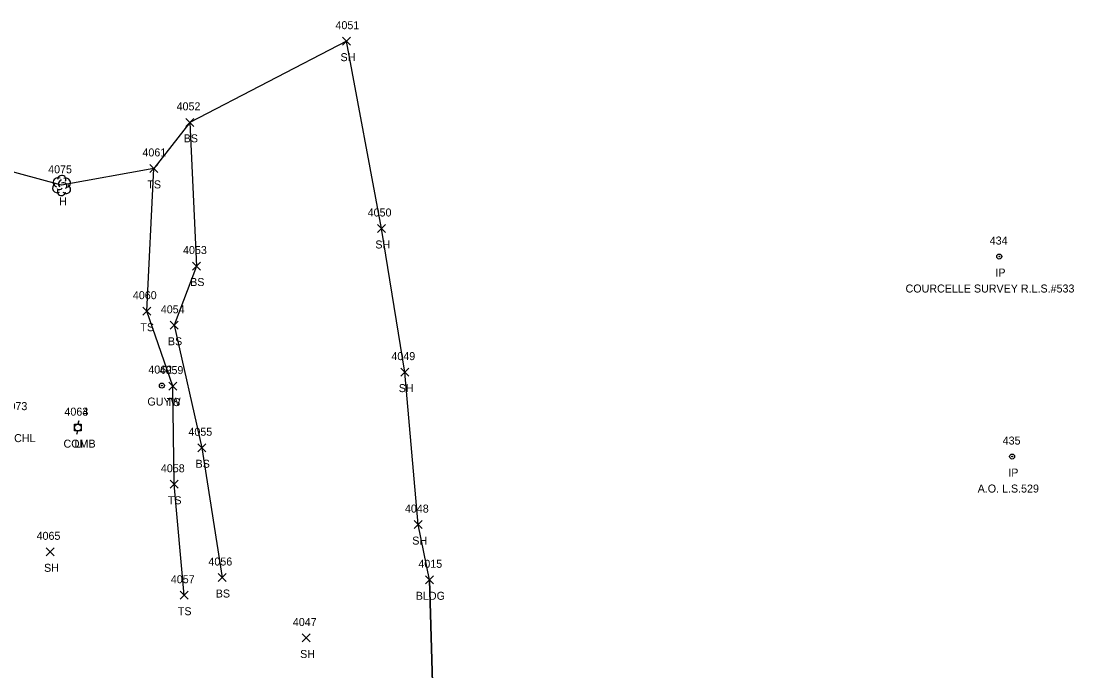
# Model space of a CAD drawing. Extents: x 1509053 to 1511576, y 400838 to 402572.
# Drawn here: x 1510649 to 1510912.2, y 401775.8 to 401938.3 of the extents above; entities that cross this region are included whole.
import ezdxf

# ---------------------------------------------------------------- set-up
doc = ezdxf.new("R2010")
doc.units = 0
for name, color, linetype in [('L_A', 7, 'Continuous'), ('L_I', 7, 'Continuous'), ('L_TIC', 7, 'Continuous'), ('LBC', 7, 'Continuous'), ('LELB', 7, 'Continuous'), ('LSOGP', 7, 'Continuous'), ('LTD', 7, 'Continuous'), ('M_A', 7, 'Continuous'), ('M_C', 7, 'Continuous'), ('M_I', 7, 'Continuous'), ('MPIR', 7, 'Continuous'), ('U_A', 7, 'Continuous'), ('U_I', 7, 'Continuous'), ('ULP', 7, 'Continuous'), ('UP', 7, 'Continuous'), ('UPGW', 7, 'Continuous')]:
    doc.layers.add(name, color=color, linetype=linetype)

msp = doc.modelspace()

# ---------------------------------------------------------------- linework, layer by layer
at = {"layer": 'L_TIC'}
for points in [[(1510729.41, 401932.32), (1510731.41, 401934.32)], [(1510731.41, 401932.32), (1510729.41, 401934.32)], [(1510690.26, 401912.02), (1510692.26, 401914.02)], [(1510692.26, 401912.02), (1510690.26, 401914.02)], [(1510681.2, 401900.5), (1510683.2, 401902.5)], [(1510683.2, 401900.5), (1510681.2, 401902.5)], [(1510738.11, 401885.48), (1510740.11, 401887.48)], [(1510740.11, 401885.48), (1510738.11, 401887.48)], [(1510691.87, 401876.09), (1510693.87, 401878.09)], [(1510693.87, 401876.09), (1510691.87, 401878.09)], [(1510679.46, 401864.8), (1510681.46, 401866.8)], [(1510681.46, 401864.8), (1510679.46, 401866.8)], [(1510686.31, 401861.27), (1510688.31, 401863.27)], [(1510688.31, 401861.27), (1510686.31, 401863.27)], [(1510743.97, 401849.56), (1510745.97, 401851.56)], [(1510745.97, 401849.56), (1510743.97, 401851.56)], [(1510686.01, 401846.07), (1510688.01, 401848.07)], [(1510688.01, 401846.07), (1510686.01, 401848.07)], [(1510693.22, 401830.65), (1510695.22, 401832.65)], [(1510695.22, 401830.65), (1510693.22, 401832.65)], [(1510686.33, 401821.52), (1510688.33, 401823.52)], [(1510688.33, 401821.52), (1510686.33, 401823.52)], [(1510747.34, 401811.44), (1510749.34, 401813.44)], [(1510749.34, 401811.44), (1510747.34, 401813.44)], [(1510655.3, 401804.63), (1510657.3, 401806.63)], [(1510657.3, 401804.63), (1510655.3, 401806.63)], [(1510698.27, 401798.2), (1510700.27, 401800.2)], [(1510700.27, 401798.2), (1510698.27, 401800.2)], [(1510750.13, 401797.63), (1510752.13, 401799.63)], [(1510752.13, 401797.63), (1510750.13, 401799.63)], [(1510688.82, 401793.77), (1510690.82, 401795.77)], [(1510690.82, 401793.77), (1510688.82, 401795.77)], [(1510719.32, 401783.08), (1510721.32, 401785.08)], [(1510721.32, 401783.08), (1510719.32, 401785.08)]]:
    msp.add_lwpolyline(points, dxfattribs=at)
at = {"layer": 'LBC'}
msp.add_lwpolyline([(1510751.13, 401798.63), (1510752.08, 401767.19), (1510771.96, 401767.6), (1510772.1, 401764.08), (1510822.61, 401765.33)], dxfattribs=at)
at = {"layer": 'LELB'}
for points in [[(1510691.26, 401913.02), (1510692.87, 401877.09), (1510687.31, 401862.27), (1510694.22, 401831.65), (1510699.27, 401799.2)], [(1510689.82, 401794.77), (1510687.33, 401822.52), (1510687.01, 401847.07), (1510680.46, 401865.8), (1510682.2, 401901.5)]]:
    msp.add_lwpolyline(points, dxfattribs=at)
at = {"layer": 'LSOGP'}
msp.add_lwpolyline([(1510752.08, 401767.19), (1510751.13, 401798.63), (1510748.34, 401812.44), (1510744.97, 401850.56), (1510739.11, 401886.48), (1510730.41, 401933.32), (1510691.26, 401913.02), (1510682.2, 401901.5), (1510659.15, 401897.28), (1510643.42, 401901.55)], dxfattribs=at)
at = {"layer": 'LTD'}
msp.add_line((1510659.15, 401897.28), (1510659.15, 401897.28), dxfattribs=at)
msp.add_line((1510659.15, 401897.28), (1510659.15, 401897.28), dxfattribs=at)
msp.add_arc((1510659.2, 401898.71), 1.05, 335.5272, 180.9563, dxfattribs=at)
for centre, major_axis, ratio, start_param, end_param in [((1510658.07, 401896.57), (0.58, -1.04), 0.959034, 3.141593, 6.283185), ((1510658.36, 401897.95), (1.21, -0.51), 0.895232, 1.570796, 4.712389), ((1510658.94, 401897.74), (-0.208, -0.792), 0.645439, 3.141593, 6.283185), ((1510659.65, 401897.11), (-0.5, 0.667), 0.989748, 3.141593, 6.283185), ((1510660.15, 401896.45), (-1.09, 0.79), 0.841452, 1.570796, 4.712389), ((1510660.19, 401897.86), (-1.14, -0.48), 0.949671, 1.570796, 4.712389), ((1510659.15, 401895.78), (0.26, 1.06), 0.942809, 1.570796, 4.712389), ((1510658.69, 401896.53), (-0.625, -0.083), 0.423636, 0, 3.141593)]:
    msp.add_ellipse(centre, major_axis=major_axis, ratio=ratio, start_param=start_param, end_param=end_param, dxfattribs=at)
at = {"layer": 'MPIR'}
for centre, radius in [((1510893.57, 401879.47), 0.625), ((1510893.57, 401879.47), 0.0833), ((1510896.79, 401829.45), 0.625), ((1510896.79, 401829.45), 0.0833)]:
    msp.add_circle(centre, radius, dxfattribs=at)
at = {"layer": 'ULP'}
for p, q in [((1510662.43, 401835.85), (1510662.43, 401837.51)), ((1510662.43, 401837.51), (1510664.09, 401837.51)), ((1510663.43, 401838.35), (1510663.26, 401837.51)), ((1510664.09, 401837.51), (1510664.09, 401835.85)), ((1510664.09, 401835.85), (1510662.43, 401835.85)), ((1510663.01, 401835.01), (1510663.26, 401835.85)), ((1510663.26, 401836.68), (1510663.26, 401836.68))]:
    msp.add_line(p, q, dxfattribs=at)
at = {"layer": 'UP'}
for p, q in [((1510662.43, 401835.85), (1510662.43, 401837.51)), ((1510662.43, 401837.51), (1510664.09, 401837.51)), ((1510663.51, 401838.35), (1510663.26, 401837.51)), ((1510664.09, 401837.51), (1510664.09, 401835.85)), ((1510664.09, 401835.85), (1510662.43, 401835.85)), ((1510663.01, 401835.01), (1510663.26, 401835.85)), ((1510663.26, 401836.68), (1510663.26, 401836.68))]:
    msp.add_line(p, q, dxfattribs=at)
msp.add_circle((1510663.26, 401836.68), 0.833, dxfattribs=at)
at = {"layer": 'UPGW'}
for radius in [0.625, 0.0833]:
    msp.add_circle((1510684.23, 401847.2), radius, dxfattribs=at)

# ---------------------------------------------------------------- texts
at = {"layer": 'L_A'}
for s, p in [('SH', (1510728.9, 401928.32)), ('BS', (1510689.7, 401908.02)), ('TS', (1510680.61, 401896.5)), ('H', (1510658.58, 401892.28)), ('SH', (1510737.6, 401881.48)), ('BS', (1510691.31, 401872.09)), ('TS', (1510678.87, 401860.8)), ('BS', (1510685.75, 401857.27)), ('SH', (1510743.46, 401845.56)), ('TS', (1510685.42, 401842.07)), ('FNCHL', (1510643.74, 401833.06)), ('BS', (1510692.66, 401826.65)), ('TS', (1510685.74, 401817.52)), ('SH', (1510746.83, 401807.44)), ('SH', (1510654.79, 401800.63)), ('BS', (1510697.71, 401794.2)), ('BLDG', (1510747.72, 401793.63)), ('TS', (1510688.23, 401789.77)), ('SH', (1510718.81, 401779.08))]:
    msp.add_text(s, height=2, dxfattribs=at).set_placement(p)
at = {"layer": 'L_I'}
for s, p in [('4051', (1510727.64, 401936.32)), ('4052', (1510687.92, 401916.02)), ('4061', (1510679.38, 401904.5)), ('4075', (1510655.81, 401900.28)), ('4050', (1510735.69, 401889.48)), ('4053', (1510689.53, 401880.09)), ('4060', (1510676.99, 401868.8)), ('4054', (1510683.97, 401865.27)), ('4049', (1510741.62, 401853.56)), ('4059', (1510683.66, 401850.07)), ('4073', (1510644.65, 401841.06)), ('4055', (1510690.88, 401834.65)), ('4058', (1510683.99, 401825.52)), ('4048', (1510745, 401815.44)), ('4065', (1510652.92, 401808.63)), ('4056', (1510695.88, 401802.2)), ('4015', (1510748.36, 401801.63)), ('4057', (1510686.48, 401797.77)), ('4047', (1510716.98, 401787.08))]:
    msp.add_text(s, height=2, dxfattribs=at).set_placement(p)
at = {"layer": 'M_A'}
for p in [(1510892.61, 401874.47), (1510895.84, 401824.45)]:
    msp.add_text('IP', height=2, dxfattribs=at).set_placement(p)
at = {"layer": 'M_C'}
for s, p in [('COURCELLE SURVEY R.L.S.#533', (1510870.15, 401870.47)), ('A.O. L.S.529', (1510888.18, 401820.45))]:
    msp.add_text(s, height=2, dxfattribs=at).set_placement(p)
at = {"layer": 'M_I'}
for s, p in [('434', (1510891.2, 401882.47)), ('435', (1510894.43, 401832.45))]:
    msp.add_text(s, height=2, dxfattribs=at).set_placement(p)
at = {"layer": 'U_A'}
for s, p in [('GUYW', (1510680.62, 401842.2)), ('COMB', (1510659.65, 401831.68)), ('LI', (1510662.36, 401831.68))]:
    msp.add_text(s, height=2, dxfattribs=at).set_placement(p)
at = {"layer": 'U_I'}
for s, p in [('4062', (1510680.85, 401850.2)), ('4063', (1510659.88, 401839.68)), ('4064', (1510659.88, 401839.68))]:
    msp.add_text(s, height=2, dxfattribs=at).set_placement(p)

doc.saveas('drawing.dxf')
